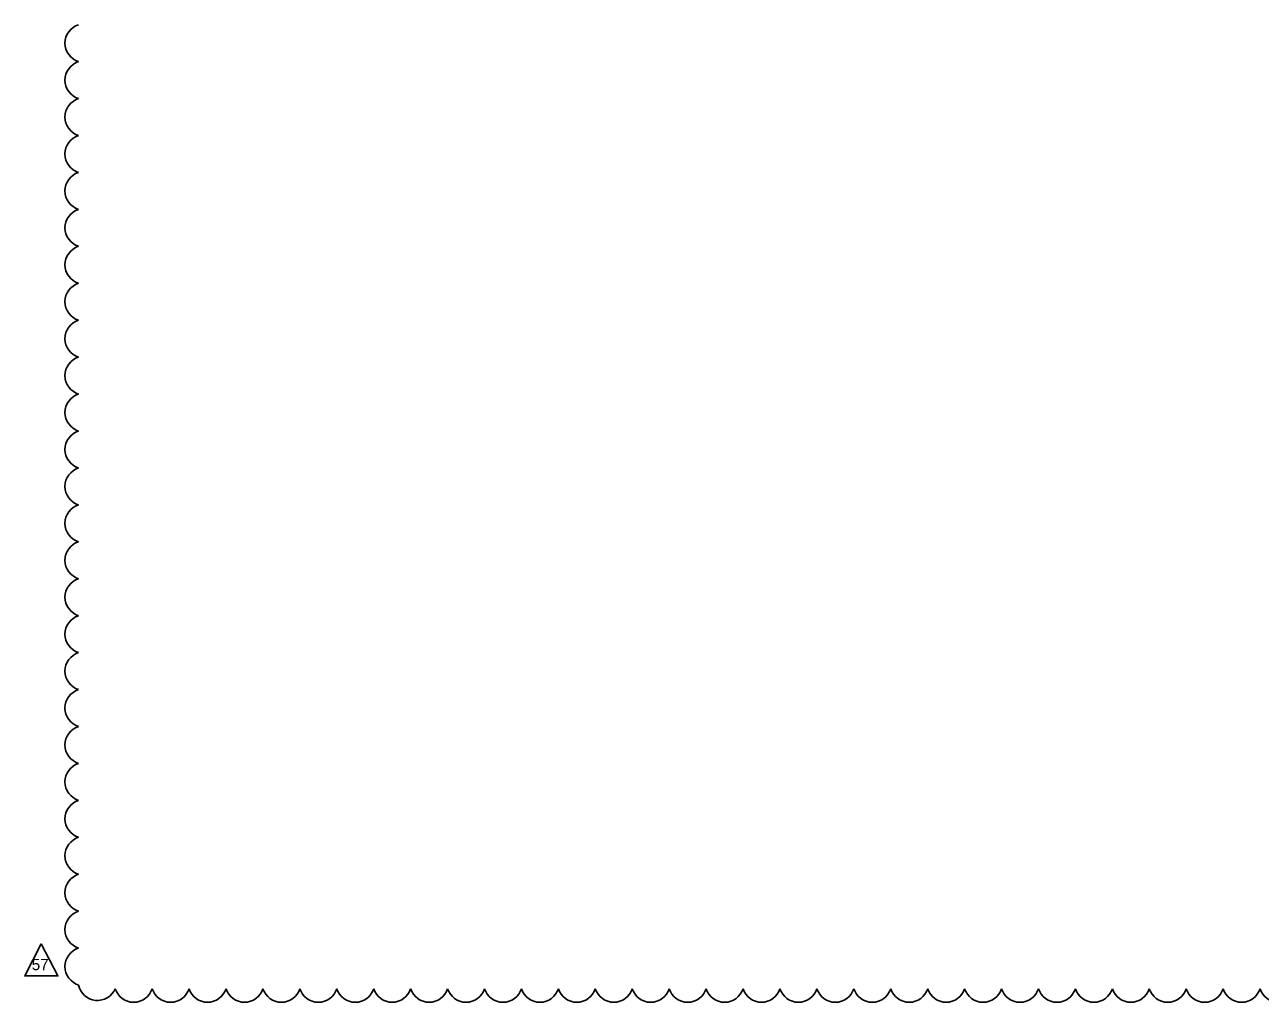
# Model space of a CAD drawing. Extents: x -811 to 10319, y -2309 to 9962.
# Drawn here: x -811.04 to -805.31, y -2198.66 to -2194.13 of the extents above; entities that cross this region are included whole.
import ezdxf

# ---------------------------------------------------------------- set-up
doc = ezdxf.new("R2010")
doc.units = 0
doc.layers.add('TextMisc', color=7, linetype='Continuous')
doc.layers.add('TextTitle', color=7, linetype='Continuous')

msp = doc.modelspace()

# ---------------------------------------------------------------- linework, layer by layer
at = {"layer": 'TextMisc'}
msp.add_lwpolyline([(-810.9581, -2198.3928), (-811.0351, -2198.5411), (-810.8811, -2198.5411)], close=True, dxfattribs=at)
at = {"layer": 'TextTitle'}
for centre, radius, start, end in [((-810.7588, -2194.2199), 0.0897, 107.5, 252.5), ((-810.7588, -2194.391), 0.0897, 107.5, 252.5), ((-810.7588, -2194.5621), 0.0897, 107.5, 252.5), ((-810.7588, -2194.7332), 0.0897, 107.5, 252.5), ((-810.7588, -2194.9044), 0.0897, 107.5, 252.5), ((-810.7588, -2195.0755), 0.0897, 107.5, 252.5), ((-810.7588, -2195.2466), 0.0897, 107.5, 252.5), ((-810.7588, -2195.4177), 0.0897, 107.5, 252.5), ((-810.7588, -2195.5889), 0.0897, 107.5, 252.5), ((-810.7588, -2195.76), 0.0897, 107.5, 252.5), ((-810.7588, -2195.9311), 0.0897, 107.5, 252.5), ((-810.7588, -2196.1022), 0.0897, 107.5, 252.5), ((-810.7588, -2196.2733), 0.0897, 107.5, 252.5), ((-810.7588, -2196.4445), 0.0897, 107.5, 252.5), ((-810.7588, -2196.6156), 0.0897, 107.5, 252.5), ((-810.7588, -2196.7867), 0.0897, 107.5, 252.5), ((-810.7588, -2196.9578), 0.0897, 107.5, 252.5), ((-810.7588, -2197.129), 0.0897, 107.5, 252.5), ((-810.7588, -2197.3001), 0.0897, 107.5, 252.5), ((-810.7588, -2197.4712), 0.0897, 107.5, 252.5), ((-810.7588, -2197.6423), 0.0897, 107.5, 252.5), ((-810.7588, -2197.8134), 0.0897, 107.5, 252.5), ((-810.7588, -2197.9846), 0.0897, 107.5, 252.5), ((-810.7588, -2198.1557), 0.0897, 107.5, 252.5), ((-810.7588, -2198.3268), 0.0897, 107.5, 252.5), ((-810.7588, -2198.4979), 0.0897, 107.5, 252.5), ((-810.698, -2198.5653), 0.0896, 191.7454, 336.7454), ((-810.5301, -2198.5737), 0.0897, 197.5, 342.5), ((-810.359, -2198.5737), 0.0897, 197.5, 342.5), ((-810.1879, -2198.5737), 0.0897, 197.5, 342.5), ((-810.0167, -2198.5737), 0.0897, 197.5, 342.5), ((-809.8456, -2198.5737), 0.0897, 197.5, 342.5), ((-809.6745, -2198.5737), 0.0897, 197.5, 342.5), ((-809.5034, -2198.5737), 0.0897, 197.5, 342.5), ((-809.3323, -2198.5737), 0.0897, 197.5, 342.5), ((-809.1611, -2198.5737), 0.0897, 197.5, 342.5), ((-808.99, -2198.5737), 0.0897, 197.5, 342.5), ((-808.8189, -2198.5737), 0.0897, 197.5, 342.5), ((-808.6478, -2198.5737), 0.0897, 197.5, 342.5), ((-808.4766, -2198.5737), 0.0897, 197.5, 342.5), ((-808.3055, -2198.5737), 0.0897, 197.5, 342.5), ((-808.1344, -2198.5737), 0.0897, 197.5, 342.5), ((-807.9633, -2198.5737), 0.0897, 197.5, 342.5), ((-807.7921, -2198.5737), 0.0897, 197.5, 342.5), ((-807.621, -2198.5737), 0.0897, 197.5, 342.5), ((-807.4499, -2198.5737), 0.0897, 197.5, 342.5), ((-807.2788, -2198.5737), 0.0897, 197.5, 342.5), ((-807.1077, -2198.5737), 0.0897, 197.5, 342.5), ((-806.9365, -2198.5737), 0.0897, 197.5, 342.5), ((-806.7654, -2198.5737), 0.0897, 197.5, 342.5), ((-806.5943, -2198.5737), 0.0897, 197.5, 342.5), ((-806.4232, -2198.5737), 0.0897, 197.5, 342.5), ((-806.252, -2198.5737), 0.0897, 197.5, 342.5), ((-806.0809, -2198.5737), 0.0897, 197.5, 342.5), ((-805.9098, -2198.5737), 0.0897, 197.5, 342.5), ((-805.7387, -2198.5737), 0.0897, 197.5, 342.5), ((-805.5676, -2198.5737), 0.0897, 197.5, 342.5), ((-805.3964, -2198.5737), 0.0897, 197.5, 342.5), ((-805.2253, -2198.5737), 0.0897, 197.5, 342.5)]:
    msp.add_arc(centre, radius, start, end, dxfattribs=at)

# ---------------------------------------------------------------- texts
at = {"layer": 'TextMisc'}
msp.add_text('57', height=0.0525, rotation=360, dxfattribs=at).set_placement((-811.0024, -2198.5147))

doc.saveas('drawing.dxf')
